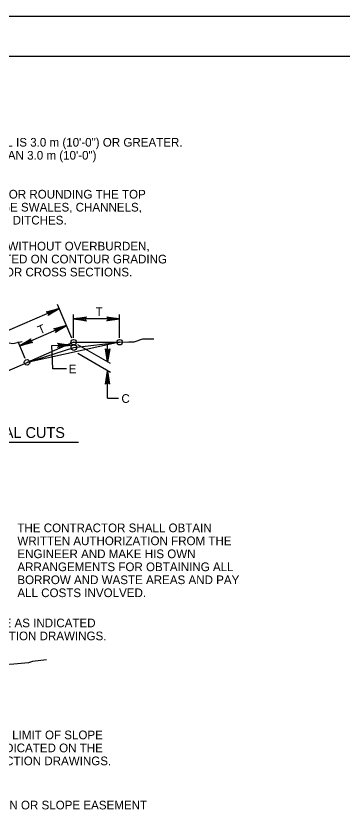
# Model space of a CAD drawing. Extents: x 240 to 1147, y 662 to 1256.
# Drawn here: x 476.2 to 597, y 959.9 to 1256 of the extents above; entities that cross this region are included whole.
import ezdxf

# ---------------------------------------------------------------- set-up
doc = ezdxf.new("R2010")
doc.units = 0
for name, color, linetype in [('1', 7, 'Continuous'), ('2', 7, 'Continuous'), ('3', 7, 'Continuous'), ('PLT-BNDY', 7, 'Continuous')]:
    doc.layers.add(name, color=color, linetype=linetype)

msp = doc.modelspace()

# ---------------------------------------------------------------- linework, layer by layer
at = {"layer": '1'}
for points in [[(1065.4425, 677.018625), (1065.4425, 1241.018625), (279.4425, 1241.018625), (279.4425, 677.018625), (1065.4425, 677.018625), (1065.4425, 703.377625), (865.4425, 703.377625), (865.4425, 768.055125), (1065.4425, 768.055125), (1065.4425, 797.018625), (865.4425, 797.018625), (865.4425, 677.018625), (944.244, 677.018625), (944.244, 703.377625), (944.244, 677.018625), (1021.244, 677.018625), (1021.244, 703.377625), (1021.244, 691.061125), (1065.4425, 691.061125)], [(487.72775, 1146.577125), (488.01325, 1146.341625), (492.12375, 1147.854125), (487.72775, 1146.577125), (487.43625, 1146.668625), (492.12375, 1147.854125), (488.19875, 1145.924875), (488.182, 1145.562375), (492.12375, 1147.854125), (488.0425, 1145.266625), (488.182, 1145.562375)], [(502.03, 1143.468625), (501.86125, 1143.797875), (497.49025, 1144.037375), (502.03, 1143.468625), (502.26325, 1143.268625), (497.49025, 1144.037375), (501.859, 1144.254125), (502.0175, 1144.579125), (497.49025, 1144.037375), (502.26325, 1144.795875), (502.0175, 1144.579125)], [(509.94875, 1144.608375), (510.1195, 1144.279125), (514.49025, 1144.037375), (509.94875, 1144.608375), (509.7175, 1144.808375), (514.49025, 1144.037375), (510.1215, 1143.822875), (509.96325, 1143.497875), (514.49025, 1144.037375), (509.7175, 1143.279125), (509.96325, 1143.497875)], [(490.42775, 1140.329125), (490.71325, 1140.093625), (494.8215, 1141.606125), (490.42775, 1140.329125), (490.134, 1140.418625), (494.8215, 1141.606125), (490.89875, 1139.674875), (490.88, 1139.314625), (494.8215, 1141.606125), (490.74025, 1139.016625), (490.88, 1139.314625)], [(481.97575, 1135.435375), (481.69025, 1135.670875), (477.582, 1134.158375), (481.97575, 1135.435375), (482.2695, 1135.345875), (477.582, 1134.158375), (481.505, 1136.087375), (481.52375, 1136.449875), (477.582, 1134.158375), (481.66325, 1136.747875), (481.52375, 1136.449875)], [(491.7945, 1134.866625), (491.9675, 1134.539625), (496.34025, 1134.335375), (491.7945, 1134.866625), (491.559, 1135.062375), (496.34025, 1134.335375), (491.97375, 1134.081125), (491.8175, 1133.754125), (496.34025, 1134.335375), (491.57375, 1133.535375), (491.8175, 1133.754125)], [(510.605, 1132.729125), (510.27775, 1132.558375), (510.03625, 1128.187375), (510.605, 1132.729125), (510.805, 1132.960375), (510.03625, 1128.187375), (509.8195, 1132.556125), (509.4945, 1132.714625), (510.03625, 1128.187375), (509.27775, 1132.960375), (509.4945, 1132.714625)], [(509.46525, 1120.199875), (509.7945, 1120.370875), (510.03625, 1124.741625), (509.46525, 1120.199875), (509.26525, 1119.968625), (510.03625, 1124.741625), (510.25075, 1120.372875), (510.57775, 1120.214625), (510.03625, 1124.741625), (510.7945, 1119.968625), (510.57775, 1120.214625)]]:
    msp.add_lwpolyline(points, dxfattribs=at)
at = {"layer": '2'}
for p, q in [((496.855, 1136.899875), (491.48825, 1149.322875)), ((492.12375, 1147.854125), (414.882, 1114.487375)), ((497.49025, 1137.031125), (497.49025, 1145.637375)), ((514.49025, 1144.037375), (497.49025, 1144.037375)), ((514.49025, 1137.031125), (514.49025, 1145.637375)), ((494.8215, 1141.606125), (477.582, 1134.158375)), ((479.61525, 1129.452125), (476.9465, 1135.627125)), ((497.49025, 1135.431125), (480.24875, 1127.983375)), ((514.49025, 1135.431125), (480.24875, 1127.983375)), ((497.49025, 1135.431125), (514.49025, 1135.431125)), ((498.87575, 1134.631125), (510.97575, 1127.643625)), ((510.03625, 1128.187375), (510.03625, 1134.706125)), ((499.0195, 1131.333375), (511.055, 1124.385375)), ((510.03625, 1114.785375), (510.03625, 1124.741625)), ((510.03625, 1114.785375), (514.007, 1114.785375)), ((451.96525, 1098.531125), (499.31125, 1098.531125))]:
    msp.add_line(p, q, dxfattribs=at)
for points in [[(478.3965, 1135.568625), (475.00275, 1134.862375), (470.88, 1135.568625), (467.484, 1136.274875), (464.57375, 1137.335375), (460.45075, 1136.983375), (454.87375, 1136.274875)], [(480.24875, 1127.983375), (497.557, 1133.449875), (514.49025, 1135.431125), (517.92775, 1135.568625), (519.8675, 1135.568625), (523.0215, 1136.629125), (525.68825, 1136.629125), (527.1445, 1136.629125)], [(494.832, 1125.612375), (489.832, 1125.612375), (489.405, 1134.274875), (496.34025, 1134.335375)], [(410.24875, 1099.183375), (420.24875, 1102.062375), (480.24875, 1127.983375)], [(487.44025, 1018.077125), (482.2465, 1017.360375), (480.832, 1016.883375), (475.32575, 1016.454125), (472.10075, 1016.166625), (467.38, 1016.406125), (461.48, 1016.406125), (456.9965, 1015.689625), (452.51125, 1015.929125), (447.82575, 1013.954125), (447.82575, 1013.954125)]]:
    msp.add_lwpolyline(points, dxfattribs=at)
for centre in [(497.490083, 1135.430375), (497.556333, 1133.449625), (514.490083, 1135.430375), (480.249333, 1127.982375)]:
    msp.add_circle(centre, 1.015435, dxfattribs=at)
at = {"layer": 'PLT-BNDY'}
msp.add_lwpolyline([(240.4425, 1256.018625), (1081.4425, 1256.018625), (1081.4425, 662.018625), (240.4425, 662.018625)], close=True, dxfattribs=at)

# ---------------------------------------------------------------- texts
at = {"layer": '2'}
for s, p in [('T', (505.62775, 1145.156125)), ('E', (495.67375, 1123.952125)), ('C', (515.13625, 1113.014625))]:
    msp.add_text(s, height=3.199988, dxfattribs=at).set_placement(p)
msp.add_text('T', height=3.199988, rotation=23.36433056, dxfattribs=at).set_placement((485.009, 1138.229125))
at = {"layer": '3'}
for s, height, p in [('*T=3.0 m (10\'-0"), WHERE L IS 3.0 m (10\'-0") OR GREATER.', 3.1999995, (420.71325, 1207.737625)), ('*T=L, WHEN L IS LESS THAN 3.0 m (10\'-0")', 3.1999995, (420.71325, 1202.939875)), (' APPLY ABOVE VALUES FOR ROUNDING THE TOP', 3.1999875, (420.71325, 1188.546625)), (' OF SLOPES OF DRAINAGE SWALES, CHANNELS,', 3.1999875, (420.71325, 1183.748875)), (' DITCHES AND PARALLEL DITCHES.', 3.1999875, (420.71325, 1178.951125)), ('*EXCEPT IN HARD ROCK WITHOUT OVERBURDEN,', 3.1999875, (420.71325, 1169.355625)), (' AND EXCEPT AS INDICATED ON CONTOUR GRADING', 3.1999875, (420.71325, 1164.557875)), (' AND DRAINAGE PLANS, OR CROSS SECTIONS.', 3.1999875, (420.71325, 1159.760125)), ('NORMAL CUTS', 3.999987, (455.32375, 1100.041625)), ('THE CONTRACTOR SHALL OBTAIN', 3.1999875, (476.68825, 1065.208375)), ('WRITTEN AUTHORIZATION FROM THE', 3.1999875, (476.68825, 1060.410375)), ('ENGINEER AND MAKE HIS OWN', 3.1999875, (476.68825, 1055.610375)), ('ARRANGEMENTS FOR OBTAINING ALL', 3.1999875, (476.68825, 1050.810375)), ('BORROW AND WASTE AREAS AND PAY', 3.1999875, (476.68825, 1046.010375)), ('ALL COSTS INVOLVED.', 3.1999875, (476.68825, 1041.210375)), ('RIGHT-OF-WAY LINE AS INDICATED', 3.1999875, (431.88625, 1030.060375)), ('ON THE CONSTRUCTION DRAWINGS.', 3.1999875, (431.88625, 1025.260375)), ('REQUIRED LIMIT OF SLOPE', 3.1999875, (450.98625, 988.670875)), ('LINE, IF INDICATED ON THE', 3.1999875, (450.98625, 983.870875)), ('CONSTRUCTION DRAWINGS.', 3.1999875, (450.98625, 979.070875)), ('CONSTRUCTION OR SLOPE EASEMENT', 3.1999875, (442.35275, 962.735375))]:
    msp.add_text(s, height=height, dxfattribs=at).set_placement(p)

doc.saveas('drawing.dxf')
